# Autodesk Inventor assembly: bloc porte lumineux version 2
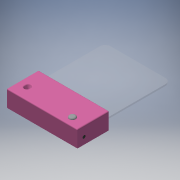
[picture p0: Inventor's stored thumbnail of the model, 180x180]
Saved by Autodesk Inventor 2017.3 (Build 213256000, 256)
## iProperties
Part Number: bloc porte lumineux version 2
Material: Générique
Document SubType Name: Assembly
Designer: ficho
Author: ficho
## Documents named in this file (10)
- C:\Users\ficho\Desktop\réforme\activité rentrée\bloc porte lumineux version 2.iam
- C:\Users\ficho\Desktop\réforme\activité rentrée\base fixe version 2.ipt
- C:\Users\ficho\Desktop\réforme\activité rentrée\capteur mm109.ipt
- C:\Users\ficho\Desktop\réforme\activité rentrée\capteur PIR.ipt
- C:\Users\ficho\Desktop\réforme\activité rentrée\couvercle coulissant.ipt
- C:\Users\ficho\OneDrive\Documents\Inventor\Content Center Files\R2017\fr-FR\ISO 7049 - C-Z(2)\ISO 7049 - ST 2,9 x 6,5 - C - Z.ipt
- C:\Users\ficho\Desktop\réforme\activité rentrée\plaque vierge.ipt
- C:\Users\ficho\Desktop\réforme\activité rentrée\stick neopixel 8 leds.iam
- C:\Users\ficho\OneDrive\Documents\Inventor\Content Center Files\R2017\fr-FR\ISO 7049 - C-Z(2)\ISO 7049 - ST 2,2 x 4,5 - C - Z.ipt
- C:\Users\ficho\OneDrive\Documents\Inventor\Content Center Files\R2017\fr-FR\ISO 7051 - C-Z(2)\ISO 7051 - ST 2,9 x 6,5 - C - Z.ipt
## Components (16 placed, 9 different names)
1. base fixe version 2:1 — Placage:1, Placage:2, Placage:3, Placage:6, Placage:7, Placage:12, Placage:13, Affleurement:1, Affleurement:2
2. capteur mm109:1 — Placage:4, Placage:5
3. capteur PIR:1 — Placage:6, Placage:7, Placage:8
4. couvercle coulissant:1 — Placage:1, Placage:2, Placage:3, Placage:4, Placage:5, Placage:8, Placage:9, Placage:10, Placage:11
5. ISO 7049 - C-Z ST 2,9 x 6,5 - C - Z:2
6. plaque vierge:1 — Placage:9, Placage:10, Placage:11
7. stick neopixel 8 leds:1 [sub-assembly] — Placage:13, Affleurement:1, Placage:15
8. stick neopixel 8 leds:2 [sub-assembly] — Placage:12, Affleurement:2
9. ISO 7049 - C-Z ST 2,2 x 4,5 - C - Z:1
10. ISO 7049 - C-Z ST 2,2 x 4,5 - C - Z:2 — Placage:15
11. ISO 7049 - C-Z ST 2,2 x 4,5 - C - Z:3
12. ISO 7049 - C-Z ST 2,2 x 4,5 - C - Z:4
13. ISO 7049 - C-Z ST 2,9 x 6,5 - C - Z:3
14. ISO 7049 - C-Z ST 2,9 x 6,5 - C - Z:4
15. ISO 7051 - C-Z ST 2,9 x 6,5 - C - Z:1
16. ISO 7051 - C-Z ST 2,9 x 6,5 - C - Z:2
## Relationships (16: Mate 14, Flush 2)
- Placage:1 [Mate]: base fixe version 2:1 ↔ couvercle coulissant:1
- Placage:2 [Mate]: base fixe version 2:1 ↔ couvercle coulissant:1
- Placage:3 [Mate]: base fixe version 2:1 ↔ couvercle coulissant:1
- Placage:4 [Mate]: capteur mm109:1 ↔ couvercle coulissant:1
- Placage:5 [Mate]: capteur mm109:1 ↔ couvercle coulissant:1
- Placage:6 [Mate]: base fixe version 2:1 ↔ capteur PIR:1
- Placage:7 [Mate]: base fixe version 2:1 ↔ capteur PIR:1
- Placage:8 [Mate]: capteur PIR:1 ↔ couvercle coulissant:1
- Placage:9 [Mate]: couvercle coulissant:1 ↔ plaque vierge:1
- Placage:10 [Mate]: couvercle coulissant:1 ↔ plaque vierge:1
- Placage:11 [Mate]: couvercle coulissant:1 ↔ plaque vierge:1
- Placage:12 [Mate]: base fixe version 2:1 ↔ stick neopixel 8 leds:2
- Placage:13 [Mate]: base fixe version 2:1 ↔ stick neopixel 8 leds:1
- Affleurement:1 [Flush]: base fixe version 2:1 ↔ stick neopixel 8 leds:1
- Affleurement:2 [Flush]: base fixe version 2:1 ↔ stick neopixel 8 leds:2
- Placage:15 [Mate]: stick neopixel 8 leds:1 ↔ ISO 7049 - C-Z ST 2,2 x 4,5 - C - Z:2
